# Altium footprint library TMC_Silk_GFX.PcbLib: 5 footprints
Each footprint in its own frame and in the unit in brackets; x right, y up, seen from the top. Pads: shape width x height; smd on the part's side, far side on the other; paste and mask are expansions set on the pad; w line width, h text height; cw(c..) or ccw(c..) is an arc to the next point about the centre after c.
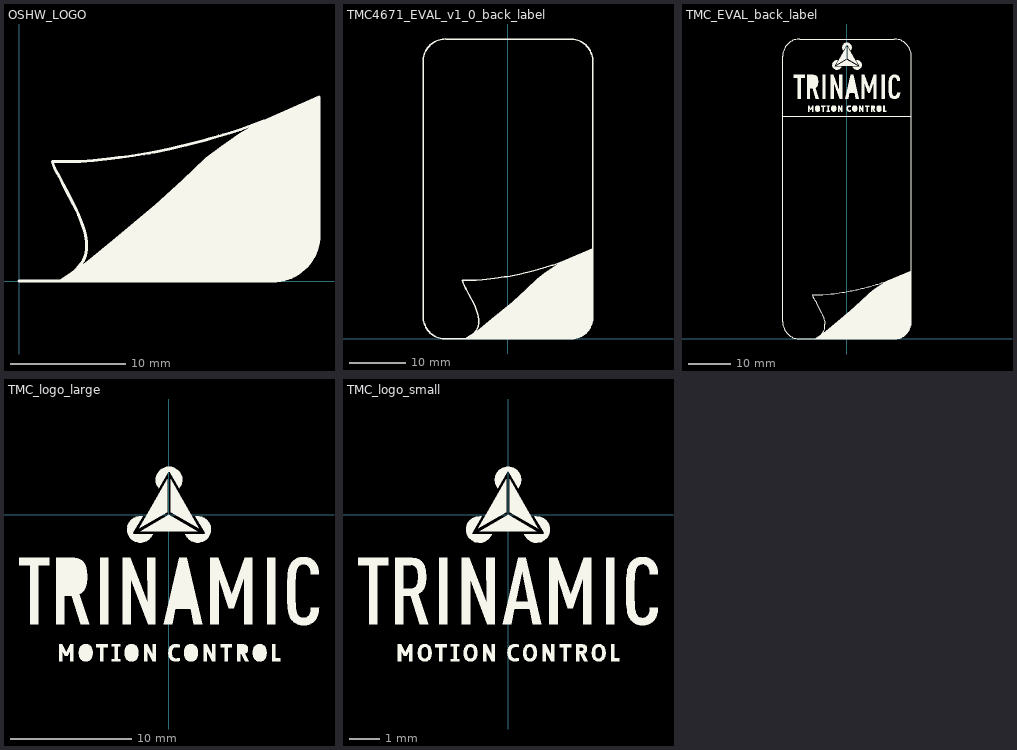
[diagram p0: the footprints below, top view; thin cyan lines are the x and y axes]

## OSHW_LOGO [mm]
Top Overlay:
  drawing of 221 lines, arcs and shapes, not listed

## TMC4671_EVAL_v1_0_back_label [mm]
Top Overlay:
  drawing of 227 lines, arcs and shapes, not listed

## TMC_EVAL_back_label [mm]
Top Overlay:
  drawing of 365 lines, arcs and shapes, not listed

## TMC_logo_large [mm]
Top Overlay:
  drawing of 137 lines, arcs and shapes, not listed

## TMC_logo_small [mm]
Top Overlay:
  drawing of 34 lines, arcs and shapes, not listed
